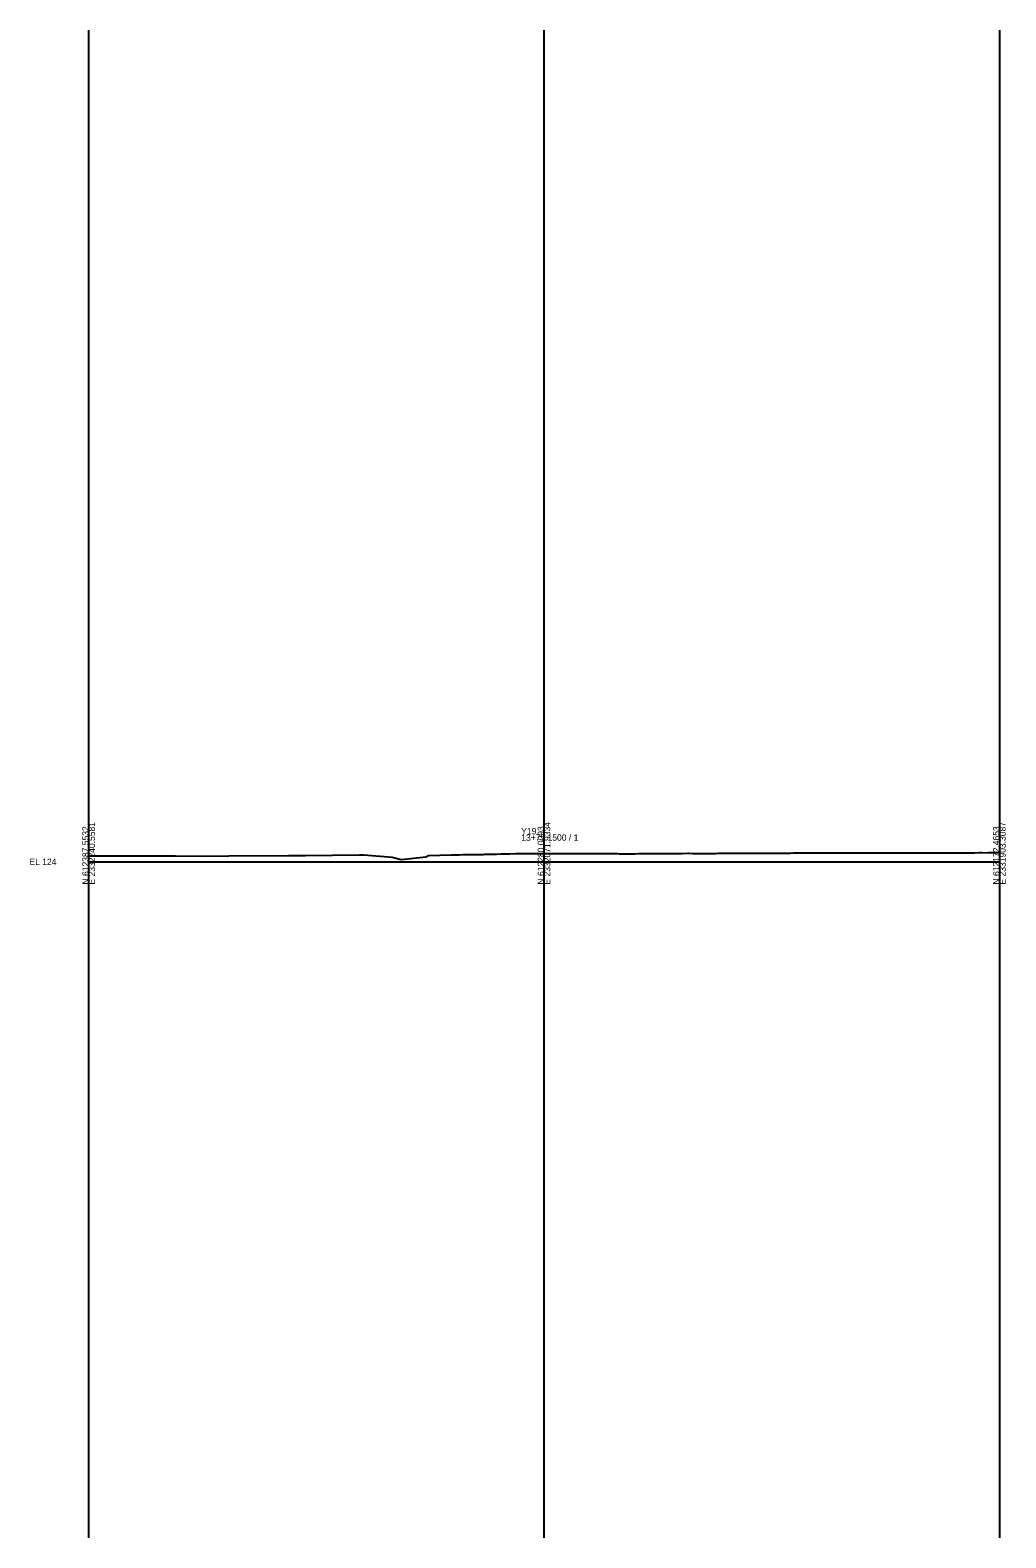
# Model space of a CAD drawing. Extents: x -26 to 2331976, y -297 to 612610.
# Drawn here: x 2774 to 3203, y -297 to 365 of the extents above; entities that cross this region are included whole.
import ezdxf

# ---------------------------------------------------------------- set-up
doc = ezdxf.new("R2010")
doc.units = 0
for name, color, linetype in [('Exist CMT Pavement', 7, 'Continuous'), ('Exist Cross Section Cell', 7, 'Continuous'), ('Exist XS Center Line Elevation Label', 7, 'Continuous'), ('Exist XS Ground Line', 7, 'Continuous'), ('Prop XS Earthwork Shape', 7, 'Continuous'), ('Prop XS Exc Vertical Line 1', 7, 'Continuous'), ('Prop XS Exc Vertical Line 2', 7, 'Continuous'), ('Prop XS Exc Vertical Line 3', 7, 'Continuous')]:
    doc.layers.add(name, color=color, linetype=linetype)

msp = doc.modelspace()

# ---------------------------------------------------------------- linework, layer by layer
at = {"layer": 'Exist CMT Pavement'}
for points in [[(2999.9, 3.63), (2999.9, 3.73), (3000, 3.73), (3000, 3.63)], [(3000, 3.63), (3000, 3.73), (3000.1, 3.73), (3000.1, 3.63)]]:
    msp.add_lwpolyline(points, dxfattribs=at)
at = {"layer": 'Exist Cross Section Cell'}
for p, q in [((3000, 0), (3000, 12.05)), ((2800, 0), (3000, 0)), ((3000, 0), (3200, 0))]:
    msp.add_line(p, q, dxfattribs=at)
at = {"layer": 'Exist XS Ground Line'}
msp.add_lwpolyline([(2800, 2.57), (2815.5, 2.64), (2838.09, 2.61), (2851.96, 2.52), (2861.61, 2.64), (2887.73, 2.77), (2891.69, 2.79), (2895.31, 2.77), (2918.96, 3.06), (2919.28, 3.07), (2920.86, 3.07), (2933.35, 2), (2937.32, 1.05), (2948.08, 2.23), (2949.29, 2.73), (2959.24, 3.03), (2960.59, 3.06), (2962.29, 3.09), (2962.77, 3.1), (2964.32, 3.13), (2964.93, 3.14), (2967.4, 3.18), (2968.71, 3.2), (2969.78, 3.22), (2970.6, 3.23), (2972.78, 3.26), (2973.44, 3.27), (2974.01, 3.28), (2975.48, 3.3), (2976.27, 3.33), (2977.33, 3.36), (2979.31, 3.4), (2981.02, 3.43), (2981.94, 3.45), (2982.87, 3.46), (2984.97, 3.52), (2987.61, 3.58), (2989.91, 3.64), (2990.45, 3.65), (2991.07, 3.65), (2993.28, 3.66), (2993.95, 3.66), (2995.2, 3.67), (2995.8, 3.67), (2996.12, 3.67), (2997.65, 3.66), (2998.95, 3.64), (2999.49, 3.64), (3000, 3.63), (3000.5, 3.63), (3001.34, 3.63), (3001.79, 3.63), (3003.19, 3.64), (3004.63, 3.65), (3005.8, 3.65), (3007.46, 3.65), (3008.73, 3.66), (3010.3, 3.66), (3011.1, 3.65), (3013.13, 3.63), (3015.47, 3.66), (3016.4, 3.66), (3017.96, 3.65), (3018.8, 3.66), (3021.7, 3.67), (3023.51, 3.66), (3024.47, 3.65), (3025.35, 3.64), (3027.31, 3.62), (3029.05, 3.61), (3030.14, 3.61), (3032.3, 3.57), (3032.98, 3.55), (3033.76, 3.55), (3035.81, 3.55), (3036.44, 3.56), (3037.6, 3.55), (3038.28, 3.55), (3038.65, 3.55), (3039.86, 3.56), (3041.49, 3.57), (3041.98, 3.57), (3042.9, 3.57), (3043.82, 3.58), (3044.32, 3.58), (3045.67, 3.58), (3047.16, 3.6), (3047.52, 3.6), (3048.19, 3.6), (3049.37, 3.61), (3049.99, 3.61), (3051.21, 3.62), (3052.83, 3.64), (3053.49, 3.64), (3055.34, 3.67), (3055.66, 3.67), (3056.75, 3.68), (3058.79, 3.69), (3060.61, 3.7), (3062.97, 3.72), (3063.61, 3.72), (3065.35, 3.69), (3065.89, 3.69), (3067.48, 3.69), (3068.6, 3.7), (3069.48, 3.69), (3071.01, 3.7), (3071.63, 3.69), (3072.95, 3.67), (3074.93, 3.7), (3075.38, 3.71), (3076.43, 3.75), (3077.02, 3.77), (3078.66, 3.78), (3079.27, 3.78), (3079.82, 3.78), (3080.91, 3.78), (3081.63, 3.78), (3082.85, 3.78), (3083.76, 3.78), (3084.72, 3.78), (3085.13, 3.79), (3085.86, 3.79), (3087.53, 3.8), (3088.05, 3.8), (3088.97, 3.8), (3090.35, 3.81), (3093.06, 3.82), (3095.16, 3.83), (3095.68, 3.83), (3097.72, 3.84), (3099.19, 3.84), (3100.15, 3.84), (3101.18, 3.85), (3102.97, 3.85), (3104.23, 3.85), (3105.3, 3.86), (3106.72, 3.86), (3108.3, 3.86), (3109.53, 3.87), (3111.97, 3.87), (3112.29, 3.87), (3113.05, 3.87), (3115.21, 3.88), (3117.08, 3.88), (3118.04, 3.88), (3119.55, 3.89), (3120.88, 3.89), (3121.4, 3.89), (3122.38, 3.89), (3123.24, 3.89), (3123.71, 3.89), (3125.09, 3.9), (3126.55, 3.89), (3126.94, 3.89), (3127.68, 3.9), (3129.38, 3.91), (3131.34, 3.9), (3132.48, 3.9), (3132.98, 3.91), (3135.05, 3.92), (3136.18, 3.91), (3137.89, 3.92), (3138.28, 3.92), (3139.87, 3.93), (3140.72, 3.93), (3141.72, 3.92), (3143.58, 3.94), (3146.39, 3.93), (3147.26, 3.93), (3149.23, 3.95), (3149.64, 3.95), (3152.07, 3.95), (3152.8, 3.95), (3154.17, 3.95), (3154.9, 3.95), (3155.74, 3.96), (3157.74, 3.96), (3159.47, 3.96), (3160.19, 3.96), (3160.57, 3.96), (3162.04, 3.96), (3163.41, 3.95), (3164.77, 3.95), (3166.24, 3.95), (3167.93, 3.95), (3169.08, 3.96), (3170.07, 3.96), (3171.91, 3.96), (3174.03, 3.96), (3174.97, 3.96), (3175.37, 3.97), (3176.81, 3.98), (3177.58, 3.98), (3178.66, 3.98), (3180.67, 3.98), (3182.35, 3.99), (3183.26, 3.99), (3184.2, 3.98), (3186.09, 3.99), (3187.89, 4), (3188.93, 4), (3191.27, 4.01), (3191.76, 4.01), (3192.33, 4.01), (3194.6, 4), (3195.22, 4.01), (3196.57, 4.01), (3197.43, 4.01), (3198.43, 4.02), (3200, 4.02)], dxfattribs=at)
at = {"layer": 'Prop XS Earthwork Shape'}
msp.add_lwpolyline([(2999.9, 3.63), (3000, 3.63), (3000, 3.73), (2999.9, 3.73)], close=True, dxfattribs=at)
msp.add_lwpolyline([(2999.9, 3.63), (3000, 3.63), (3000, 3.73), (2999.9, 3.73)], close=True, dxfattribs=at)
at = {"layer": 'Prop XS Exc Vertical Line 1'}
msp.add_line((2800, -297.11), (2800, 365.48), dxfattribs=at)
at = {"layer": 'Prop XS Exc Vertical Line 2'}
msp.add_line((3000, -297.11), (3000, 365.48), dxfattribs=at)
at = {"layer": 'Prop XS Exc Vertical Line 3'}
msp.add_line((3200, 365.48), (3200, -297.11), dxfattribs=at)

# ---------------------------------------------------------------- texts
at = {"layer": 'Exist Cross Section Cell'}
for s, p in [('N 612387.5532', (2800, -10)), ('E 2332240.5581', (2802.8, -10)), ('N 612280.0093', (3000, -10)), ('E 2332071.9334', (3002.8, -10)), ('N 612172.4653', (3200, -10)), ('E 2331903.3087', (3202.8, -10))]:
    msp.add_text(s, height=2.8, rotation=90, dxfattribs=at).set_placement(p)
for s, p in [('Y19', (2990, 12.05)), ('13+79.1500 / 1', (2990, 9.25)), ('EL 124', (2774, -1.4))]:
    msp.add_text(s, height=2.8, dxfattribs=at).set_placement(p)
at = {"layer": 'Exist XS Center Line Elevation Label'}
msp.add_text('127.63', height=0.2, dxfattribs=at).set_placement((2999.61, 1.63))

doc.saveas('drawing.dxf')
